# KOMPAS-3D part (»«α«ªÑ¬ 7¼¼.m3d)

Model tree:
1. Эскиз:1
2. Операция выдавливания:1
     Расстояние 1 = 8
3. Эскиз:2
4. Операция выдавливания:2
     Расстояние 1 = 1
5. Эскиз:3
6. Операция выдавливания:3
     Расстояние 1 = 2.5; Угол 1 = 8
7. Эскиз:4
8. Вырезать элемент выдавливания:1
     Расстояние 1 = 20
9. Эскиз:5
10. Вырезать элемент выдавливания:2
     Расстояние 1 = 3; Угол 1 = 19
11. Скругление:1
     Радиус = 1
12. Скругление:2
     Радиус = 1
13. Скругление:3
     Радиус = 1
14. Эскиз:6
15. Эскиз:7
16. Вырезать элемент выдавливания:3
     Расстояние 2 = 30; Расстояние 1 = 60
17. Эскиз:8
18. Вырезать элемент выдавливания:4
     Расстояние 2 = 30; Расстояние 1 = 60
19. Эскиз:9
20. Операция выдавливания:4
     Расстояние 1 = 10; Расстояние 2 = 62
21. Эскиз:10
22. Вырезать элемент выдавливания:5
     Расстояние 2 = 30; Расстояние 1 = 60
23. Скругление:4
     Радиус = 2
24. Скругление:5
     Радиус = 2
25. Эскиз:11
26. Вырезать элемент выдавливания:6
     Расстояние 1 = 10
27. Эскиз:12
28. Вырезать элемент выдавливания:7
     Расстояние 1 = 2.5; Угол 1 = 3
29. Эскиз:13
30. Вырезать элемент выдавливания:8
     Расстояние 2 = 40; Расстояние 1 = 30
31. Эскиз:14
32. Операция выдавливания:5
     Расстояние 1 = 10
33. Операция выдавливания:6
     Расстояние 1 = 2.5; Расстояние 2 = 5.94316
34. Эскиз:15
35. Вырезать элемент выдавливания:9
     Расстояние 1 = 20
36. Эскиз:16
37. Вырезать элемент выдавливания:10
     Расстояние 1 = 10
